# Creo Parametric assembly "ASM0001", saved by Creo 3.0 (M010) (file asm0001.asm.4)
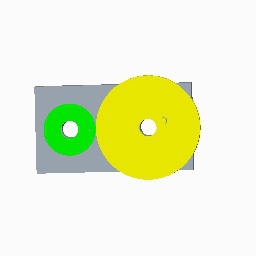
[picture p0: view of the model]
Units: millimeter Newton Second (mmNs); MM, TONNE, SECS

Created from: INLBS_ASM_DESIGN.ASM

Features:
  1. datum plane "ASM_RIGHT"
  2. datum plane "ASM_TOP"
  3. datum plane "ASM_FRONT"
  4. coordinate system
  5. coordinate system
  6. component "GEAR_BASE"
  7. component "GEAR001"
  8. component "GEAR002"

Other named items: ACS0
